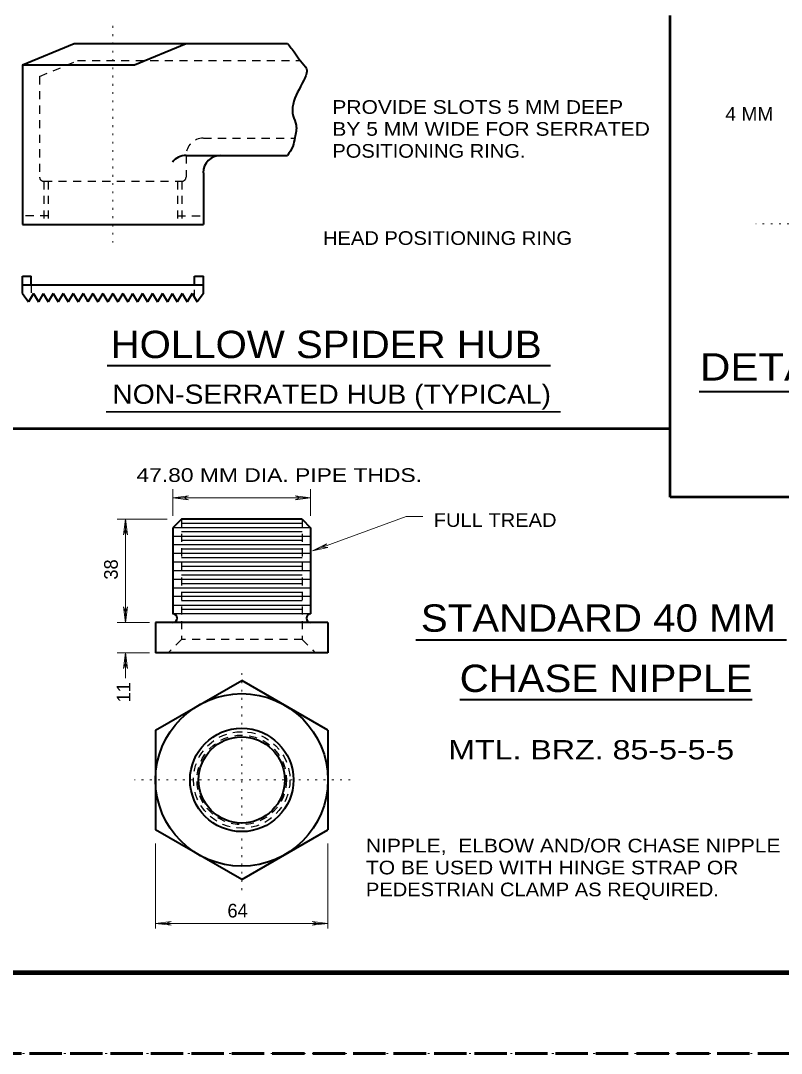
# Model space of a CAD drawing. Extents: x 312583 to 312854, y 144419 to 144597.
# Drawn here: x 312620 to 312662.3, y 144418.6 to 144476 of the extents above; entities that cross this region are included whole.
import ezdxf
from ezdxf.enums import TextEntityAlignment as Align

# ---------------------------------------------------------------- set-up
doc = ezdxf.new("R2010")
doc.units = 0
doc.header["$LTSCALE"] = 0.3
for name, pattern in [('DOTTED', [1.5, 0.3, -1.2]), ('LONG_DASHED', [7.5, 6, -1.5]), ('SHORT_DASHED', [2.7, 1.5, -1.2])]:
    doc.linetypes.add(name, pattern=pattern)
for name, color, linetype, lineweight in [('1', 7, 'Continuous', 40), ('2', 7, 'Continuous', 13), ('62', 7, 'DOTTED', 13), ('63', 7, 'LONG_DASHED', 60)]:
    doc.layers.add(name, color=color, linetype=linetype, lineweight=lineweight)

msp = doc.modelspace()

# ---------------------------------------------------------------- linework, layer by layer
at = {"layer": '1', "lineweight": 53}
for p, q in [((312656.0838, 144449.509), (312656.0838, 144476.2913)), ((312656.0838, 144453.2989), (312616.5, 144453.2989)), ((312725.6321, 144449.509), (312656.0838, 144449.509))]:
    msp.add_line(p, q, dxfattribs=at)
at = {"layer": '1', "linetype": 'DOTTED', "lineweight": 13}
for p, q in [((312625.0786, 144475.7009), (312625.0786, 144463.6719)), ((312632.2499, 144427.6598), (312632.2499, 144439.8728)), ((312638.2836, 144433.7854), (312626.2776, 144433.7854))]:
    msp.add_line(p, q, dxfattribs=at)
at = {"layer": '1'}
for p, q in [((312620.0493, 144473.5389), (312622.9243, 144474.7349)), ((312622.9243, 144474.7349), (312634.7923, 144474.7349)), ((312626.2823, 144473.5389), (312629.1573, 144474.7349)), ((312620.0493, 144473.5389), (312620.0493, 144464.6686)), ((312620.0493, 144473.5389), (312626.2823, 144473.5389)), ((312629.1573, 144468.5019), (312634.7923, 144468.5019)), ((312630.1156, 144467.5436), (312630.1156, 144464.6686)), ((312620.0493, 144464.6686), (312630.1156, 144464.6686)), ((312620.0493, 144461.7936), (312620.5323, 144461.7936)), ((312620.0493, 144460.8353), (312620.0493, 144461.7936)), ((312620.5323, 144461.3183), (312620.5323, 144461.7936)), ((312629.6326, 144461.7936), (312630.1156, 144461.7936)), ((312629.6326, 144461.3183), (312629.6326, 144461.7936)), ((312630.1156, 144460.8353), (312630.1156, 144461.7936)), ((312620.0493, 144461.3183), (312630.1156, 144461.3183)), ((312620.0493, 144460.8353), (312620.3866, 144460.3599)), ((312620.6626, 144460.8353), (312620.3866, 144460.3599)), ((312620.6626, 144460.8353), (312620.9386, 144460.3599)), ((312621.2146, 144460.8353), (312620.9386, 144460.3599)), ((312621.2146, 144460.8353), (312621.4906, 144460.3599)), ((312621.7666, 144460.8353), (312621.4906, 144460.3599)), ((312621.7666, 144460.8353), (312622.0426, 144460.3599)), ((312622.3186, 144460.8353), (312622.0426, 144460.3599)), ((312622.3186, 144460.8353), (312622.5946, 144460.3599)), ((312622.8706, 144460.8353), (312622.5946, 144460.3599)), ((312622.8706, 144460.8353), (312623.1466, 144460.3599)), ((312623.4226, 144460.8353), (312623.1466, 144460.3599)), ((312623.4226, 144460.8353), (312623.6986, 144460.3599)), ((312623.9746, 144460.8353), (312623.6986, 144460.3599)), ((312623.9746, 144460.8353), (312624.2506, 144460.3599)), ((312624.5266, 144460.8353), (312624.2506, 144460.3599)), ((312624.5266, 144460.8353), (312624.8026, 144460.3599)), ((312625.0786, 144460.8353), (312624.8026, 144460.3599)), ((312625.0786, 144460.8353), (312625.3546, 144460.3599)), ((312625.6306, 144460.8353), (312625.3546, 144460.3599)), ((312625.6306, 144460.8353), (312625.9066, 144460.3599)), ((312626.1826, 144460.8353), (312625.9066, 144460.3599)), ((312626.1826, 144460.8353), (312626.4586, 144460.3599)), ((312626.7346, 144460.8353), (312626.4586, 144460.3599)), ((312626.7346, 144460.8353), (312627.0106, 144460.3599)), ((312627.2866, 144460.8353), (312627.0106, 144460.3599)), ((312627.2866, 144460.8353), (312627.5626, 144460.3599)), ((312627.8386, 144460.8353), (312627.5626, 144460.3599)), ((312627.8386, 144460.8353), (312628.1146, 144460.3599)), ((312628.3906, 144460.8353), (312628.1146, 144460.3599)), ((312628.3906, 144460.8353), (312628.6666, 144460.3599)), ((312628.9426, 144460.8353), (312628.6666, 144460.3599)), ((312628.9426, 144460.8353), (312629.2186, 144460.3599)), ((312629.4946, 144460.8353), (312629.2186, 144460.3599)), ((312629.4946, 144460.8353), (312629.7706, 144460.3599)), ((312630.1156, 144460.8353), (312629.7706, 144460.3599)), ((312628.8996, 144448.2831), (312628.4166, 144447.8078)), ((312635.6079, 144448.2831), (312628.8996, 144448.2831)), ((312635.6079, 144448.2831), (312636.0832, 144447.8078)), ((312628.4166, 144447.8078), (312628.4166, 144443.0161)), ((312636.0832, 144447.8078), (312636.0832, 144443.0161)), ((312627.4582, 144442.5331), (312627.4582, 144440.8541)), ((312637.0416, 144442.5331), (312627.4582, 144442.5331)), ((312637.0416, 144442.5331), (312637.0416, 144440.8541)), ((312637.0416, 144440.8541), (312627.4582, 144440.8541)), ((312627.4582, 144436.5531), (312632.2499, 144439.3208)), ((312637.0416, 144436.5531), (312632.2499, 144439.3208)), ((312627.4582, 144436.5531), (312627.4582, 144431.0178)), ((312637.0416, 144436.5531), (312637.0416, 144431.0178)), ((312632.2499, 144428.2501), (312627.4582, 144431.0178)), ((312632.2499, 144428.2501), (312637.0416, 144431.0178))]:
    msp.add_line(p, q, dxfattribs=at)
at = {"layer": '1', "linetype": 'SHORT_DASHED', "lineweight": 25}
for p, q in [((312621.0076, 144472.8949), (312623.1159, 144473.7766)), ((312623.1159, 144473.7766), (312635.5129, 144473.7766)), ((312621.0076, 144472.8949), (312621.0076, 144467.3059)), ((312630.1156, 144469.4603), (312635.1986, 144469.4603)), ((312629.1573, 144468.5019), (312629.1573, 144467.3059)), ((312621.2453, 144467.0683), (312621.2453, 144464.6686)), ((312621.2529, 144467.0683), (312628.9196, 144467.0683)), ((312621.4906, 144467.0683), (312621.4906, 144464.6686)), ((312628.6743, 144467.0683), (312628.6743, 144464.6686)), ((312628.9119, 144467.0683), (312628.9119, 144464.6686)), ((312621.4906, 144465.1516), (312620.0493, 144465.1516)), ((312628.6743, 144465.1516), (312630.1156, 144465.1516)), ((312620.5323, 144461.3183), (312620.5323, 144460.6129)), ((312629.6326, 144460.5899), (312629.6326, 144461.3183)), ((312628.8996, 144448.2831), (312628.8996, 144441.5901)), ((312635.6079, 144448.2831), (312635.6079, 144441.5901)), ((312628.8996, 144441.5901), (312628.1789, 144440.8771)), ((312635.6079, 144441.5901), (312628.8996, 144441.5901)), ((312635.6079, 144441.5901), (312636.3209, 144440.8771))]:
    msp.add_line(p, q, dxfattribs=at)
at = {"layer": '1', "lineweight": 25}
for p, q in [((312635.6079, 144448.0454), (312628.8996, 144448.0454)), ((312636.0832, 144447.8078), (312628.4166, 144447.8078)), ((312635.6079, 144447.5701), (312628.8996, 144447.5701)), ((312636.0832, 144447.3248), (312628.4166, 144447.3248)), ((312636.0832, 144446.8494), (312628.4166, 144446.8494)), ((312635.6079, 144447.0871), (312628.8996, 144447.0871)), ((312636.0832, 144446.3664), (312628.4166, 144446.3664)), ((312635.6079, 144446.6118), (312628.8996, 144446.6118)), ((312636.0832, 144445.8911), (312628.4166, 144445.8911)), ((312635.6079, 144446.1288), (312628.8996, 144446.1288)), ((312635.6079, 144445.6534), (312628.8996, 144445.6534)), ((312636.0832, 144445.4081), (312628.4166, 144445.4081)), ((312635.6079, 144445.1704), (312628.8996, 144445.1704)), ((312636.0832, 144444.9328), (312628.4166, 144444.9328)), ((312635.6079, 144444.6951), (312628.8996, 144444.6951)), ((312636.0832, 144444.4498), (312628.4166, 144444.4498)), ((312636.0832, 144443.9744), (312628.4166, 144443.9744)), ((312635.6079, 144444.2121), (312628.8996, 144444.2121)), ((312636.0832, 144443.4914), (312628.4166, 144443.4914)), ((312635.6079, 144443.7368), (312628.8996, 144443.7368)), ((312636.0832, 144443.0161), (312628.4166, 144443.0161)), ((312635.6079, 144443.2538), (312628.8996, 144443.2538))]:
    msp.add_line(p, q, dxfattribs=at)
at = {"layer": '1', "lineweight": 158}
msp.add_line((312616.5, 144423.0846), (312849, 144423.0846), dxfattribs=at)
at = {"layer": '1'}
for radius in [4.7961, 2.875, 2.3958]:
    msp.add_circle((312632.2499, 144433.7854), radius, dxfattribs=at)
at = {"layer": '1', "linetype": 'SHORT_DASHED', "lineweight": 25}
for radius in [2.6833, 2.4917]:
    msp.add_circle((312632.2499, 144433.7854), radius, dxfattribs=at)
for centre, radius, start, end in [((312630.1118, 144468.5019), 0.9583, 90, 180), ((312621.2472, 144467.304), 0.2396, 180, 270), ((312628.9139, 144467.304), 0.2396, 270, 0)]:
    msp.add_arc(centre, radius, start, end, dxfattribs=at)
at = {"layer": '1'}
for centre, radius, start, end in [((312629.1534, 144467.5436), 0.9583, 90, 141.73857), ((312631.0701, 144467.5436), 0.9583, 90, 180), ((312628.4166, 144442.7708), 0.2396, 270, 90), ((312636.0832, 144442.7708), 0.2396, 90, 270)]:
    msp.add_arc(centre, radius, start, end, dxfattribs=at)
msp.add_spline([(312634.7923, 144474.7349), (312635.2063, 144474.1983), (312635.5129, 144473.7689), (312635.8503, 144473.3089), (312635.7046, 144472.6879), (312635.1066, 144471.3386), (312635.1066, 144470.6946), (312635.2753, 144470.1886), (312635.2063, 144469.4909), (312635.0836, 144469.0079), (312634.7923, 144468.5019)], degree=3, dxfattribs=at)
at = {"layer": '2', "linetype": 'DOTTED'}
msp.add_line((312665.9151, 144464.6993), (312660.8398, 144464.6993), dxfattribs=at)
at = {"layer": '2', "lineweight": 40}
for p, q in [((312624.7645, 144456.8251), (312649.4266, 144456.8251)), ((312657.6856, 144455.3865), (312699.411, 144455.3865)), ((312641.9296, 144441.5642), (312662.5522, 144441.5642)), ((312644.3745, 144438.2474), (312660.6388, 144438.2474))]:
    msp.add_line(p, q, dxfattribs=at)
at = {"layer": '2', "lineweight": 35}
msp.add_line((312624.709, 144454.2456), (312649.9735, 144454.2456), dxfattribs=at)
at = {"layer": '2'}
for p, q in [((312628.4166, 144448.4671), (312628.4166, 144449.9544)), ((312636.0832, 144448.4671), (312636.0832, 144449.9544)), ((312628.4166, 144449.4714), (312629.2829, 144449.5788)), ((312628.4166, 144449.4714), (312636.0832, 144449.4714)), ((312628.4166, 144449.4714), (312629.2829, 144449.3641)), ((312629.2829, 144449.5788), (312629.0069, 144449.4714)), ((312629.2829, 144449.3641), (312629.0069, 144449.4714)), ((312635.2169, 144449.5788), (312635.4929, 144449.4714)), ((312636.0832, 144449.4714), (312635.2169, 144449.5788)), ((312635.2169, 144449.3641), (312635.4929, 144449.4714)), ((312636.0832, 144449.4714), (312635.2169, 144449.3641)), ((312628.1099, 144448.2831), (312625.3192, 144448.2831)), ((312625.7869, 144448.2831), (312625.6796, 144447.4168)), ((312625.7869, 144442.5331), (312625.7869, 144448.2831)), ((312625.7869, 144448.2831), (312625.8942, 144447.4168)), ((312625.6796, 144447.4168), (312625.7869, 144447.6928)), ((312625.8942, 144447.4168), (312625.7869, 144447.6928)), ((312636.1906, 144446.5121), (312636.9649, 144446.9108)), ((312636.9649, 144446.9108), (312636.7426, 144446.7191)), ((312636.1906, 144446.5121), (312637.0416, 144446.7114)), ((312637.0416, 144446.7114), (312636.7426, 144446.7191)), ((312625.6796, 144443.3994), (312625.7869, 144443.1234)), ((312625.7869, 144442.5331), (312625.6796, 144443.3994)), ((312625.8942, 144443.3994), (312625.7869, 144443.1234)), ((312625.7869, 144442.5331), (312625.8942, 144443.3994)), ((312627.1286, 144442.5331), (312625.3192, 144442.5331)), ((312627.1286, 144440.8541), (312625.3192, 144440.8541)), ((312625.7869, 144440.8541), (312625.6796, 144439.9878)), ((312625.7869, 144439.4511), (312625.7869, 144440.8541)), ((312625.7869, 144440.8541), (312625.8942, 144439.9878)), ((312625.6796, 144439.9878), (312625.7869, 144440.2638)), ((312625.8942, 144439.9878), (312625.7869, 144440.2638)), ((312627.4582, 144430.2588), (312627.4582, 144425.5208)), ((312637.0416, 144430.2588), (312637.0416, 144425.5208)), ((312627.4582, 144425.8121), (312628.3246, 144425.9194)), ((312627.4582, 144425.8121), (312637.0416, 144425.8121)), ((312627.4582, 144425.8121), (312628.3246, 144425.7048)), ((312628.3246, 144425.9194), (312628.0486, 144425.8121)), ((312628.3246, 144425.7048), (312628.0486, 144425.8121)), ((312636.1752, 144425.9194), (312636.4512, 144425.8121)), ((312637.0416, 144425.8121), (312636.1752, 144425.9194)), ((312636.1752, 144425.7048), (312636.4512, 144425.8121)), ((312637.0416, 144425.8121), (312636.1752, 144425.7048))]:
    msp.add_line(p, q, dxfattribs=at)
msp.add_lwpolyline([(312636.1906, 144446.5121), (312641.3886, 144448.4211), (312642.3239, 144448.4211)], dxfattribs=at)
at = {"layer": '62'}
msp.add_lwpolyline([(312601.2, 144418.5846), (312853.5, 144418.5846), (312853.5, 144596.7846)], dxfattribs=at)
at = {"layer": '63'}
msp.add_line((312851.75, 144418.5846), (312583.526, 144418.5846), dxfattribs=at)

# ---------------------------------------------------------------- texts
at = {"layer": '2'}
for s, width, p in [('PROVIDE SLOTS 5 MM DEEP', 1.15, (312637.2895, 144470.8158)), ('4 MM', 1.05, (312659.1496, 144470.4311)), ('BY 5 MM WIDE FOR SERRATED', 1.15, (312637.2895, 144469.5958)), ('POSITIONING RING.', 1.1, (312637.2895, 144468.3758)), ('HEAD POSITIONING RING', 1.1, (312636.7703, 144463.5296)), ('47.80 MM DIA. PIPE THDS.', 1.25, (312626.3924, 144450.3526)), ('FULL TREAD', 1.1, (312642.9257, 144447.8533)), ('NIPPLE,  ELBOW AND/OR CHASE NIPPLE', 1.15, (312639.1576, 144429.7549)), ('TO BE USED WITH HINGE STRAP OR', 1.15, (312639.1576, 144428.5349)), ('PEDESTRIAN CLAMP AS REQUIRED.', 1.1, (312639.1576, 144427.3149))]:
    msp.add_text(s, height=0.76, dxfattribs=dict(at, width=width)).set_placement(p)
for s, height, width, p in [('HOLLOW SPIDER HUB', 1.52, 1.1, (312636.9437, 144457.2366)), ('DETAIL OF HEAD POSITIONING RING', 1.52, 1.15, (312678.5854, 144455.9871)), ('NON-SERRATED HUB (TYPICAL)', 1.07, 1.1, (312637.2495, 144454.6959)), ('STANDARD 40 MM', 1.52, 1.1, (312652.0911, 144442.0243)), ('CHASE NIPPLE', 1.52, 1.1, (312652.5114, 144438.6738)), ('MTL. BRZ. 85-5-5-5', 1.07, 1.25, (312651.6854, 144434.9276))]:
    msp.add_text(s, height=height, dxfattribs=dict(at, width=width)).set_placement(p, align=Align.CENTER)
for s, p in [('38', (312625.3563, 144444.9194)), ('11 ', (312626.0607, 144438.0934))]:
    msp.add_text(s, height=0.76, rotation=90, dxfattribs=at).set_placement(p)
msp.add_text('64', height=0.76, dxfattribs=at).set_placement((312631.455, 144426.1384))

doc.saveas('drawing.dxf')
